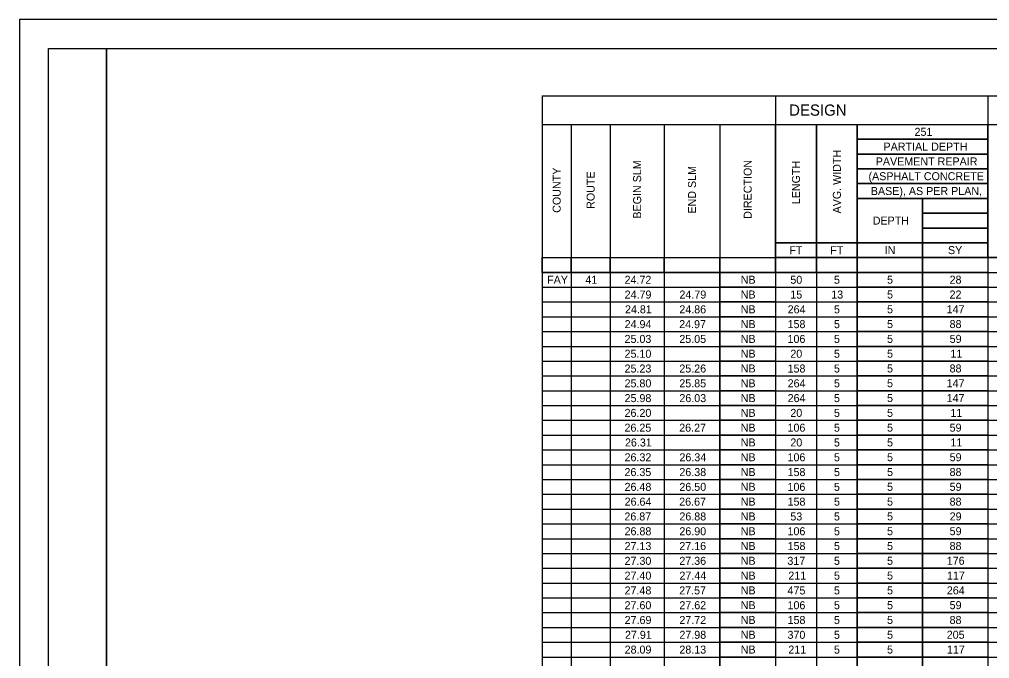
# Model space of a CAD drawing. Extents: x 0 to 34, y 0 to 22.
# Drawn here: x 0 to 16.72, y 10.98 to 22 of the extents above; entities that cross this region are included whole.
import ezdxf

# ---------------------------------------------------------------- set-up
doc = ezdxf.new("R2010")
doc.units = 0
for name, color, linetype in [('SH_Border', 7, 'Continuous'), ('SH_Cut_Line', 7, 'Continuous'), ('SH_Text', 7, 'Continuous')]:
    doc.layers.add(name, color=color, linetype=linetype)

msp = doc.modelspace()

# ---------------------------------------------------------------- linework, layer by layer
at = {"layer": 'SH_Border'}
for points in [[(0.5, 21.5), (1.5, 21.5), (1.5, 0.5), (0.5, 0.5)], [(1.5, 21.5), (33.5, 21.5), (33.5, 0.5), (1.5, 0.5)]]:
    msp.add_lwpolyline(points, close=True, dxfattribs=at)
at = {"layer": 'SH_Cut_Line'}
msp.add_lwpolyline([(0, 0), (34, 0), (34, 22), (0, 22)], close=True, dxfattribs=at)
at = {"layer": 'SH_Text'}
for p, q in [((9.014, 20.684), (23.069, 20.684)), ((9.014, 20.684), (9.014, 1.829)), ((13.034, 20.684), (13.034, 2.084)), ((16.694, 20.684), (16.694, 1.829)), ((9.014, 20.189), (23.069, 20.189)), ((9.509, 20.189), (9.509, 2.084)), ((10.184, 20.189), (10.184, 2.084)), ((11.114, 20.189), (11.114, 2.084)), ((12.074, 20.189), (12.074, 2.084)), ((13.739, 20.189), (13.739, 2.084)), ((14.444, 20.189), (14.444, 1.829)), ((14.444, 19.934), (16.694, 19.934)), ((14.444, 18.914), (15.569, 18.914)), ((15.569, 18.914), (15.569, 2.084)), ((13.034, 18.149), (16.694, 18.149)), ((9.014, 17.894), (23.069, 17.894)), ((9.014, 17.639), (23.069, 17.639)), ((9.014, 17.384), (23.069, 17.384)), ((9.014, 17.129), (23.069, 17.129)), ((9.014, 16.874), (23.069, 16.874)), ((9.014, 16.619), (23.069, 16.619)), ((9.014, 16.364), (23.069, 16.364)), ((9.014, 16.109), (23.069, 16.109)), ((9.014, 15.854), (23.069, 15.854)), ((9.014, 15.599), (23.069, 15.599)), ((9.014, 15.344), (23.069, 15.344)), ((9.014, 15.089), (23.069, 15.089)), ((9.014, 14.834), (23.069, 14.834)), ((9.014, 14.579), (23.069, 14.579)), ((9.014, 14.324), (23.069, 14.324)), ((9.014, 14.069), (23.069, 14.069)), ((9.014, 13.814), (23.069, 13.814)), ((9.014, 13.559), (23.069, 13.559)), ((9.014, 13.304), (23.069, 13.304)), ((9.014, 13.049), (23.069, 13.049)), ((9.014, 12.794), (23.069, 12.794)), ((9.014, 12.539), (23.069, 12.539)), ((9.014, 12.284), (23.069, 12.284)), ((9.014, 12.029), (23.069, 12.029)), ((9.014, 11.774), (23.069, 11.774)), ((9.014, 11.519), (23.069, 11.519)), ((9.014, 11.264), (23.069, 11.264)), ((9.014, 11.009), (23.069, 11.009))]:
    msp.add_line(p, q, dxfattribs=at)
for points in [[(13.034, 20.189), (13.739, 20.189), (13.739, 18.149), (13.034, 18.149)], [(13.739, 20.189), (14.444, 20.189), (14.444, 18.149), (13.739, 18.149)], [(14.444, 20.189), (16.694, 20.189), (16.694, 19.934), (14.444, 19.934)], [(16.694, 20.189), (23.069, 20.189), (23.069, 17.894), (16.694, 17.894)], [(14.444, 19.934), (16.694, 19.934), (16.694, 19.679), (14.444, 19.679)], [(14.444, 19.679), (16.694, 19.679), (16.694, 19.424), (14.444, 19.424)], [(14.444, 19.424), (16.694, 19.424), (16.694, 19.169), (14.444, 19.169)], [(14.444, 19.169), (16.694, 19.169), (16.694, 18.914), (14.444, 18.914)], [(14.444, 18.914), (15.569, 18.914), (15.569, 18.149), (14.444, 18.149)], [(15.569, 18.914), (16.694, 18.914), (16.694, 18.659), (15.569, 18.659)], [(15.569, 18.659), (16.694, 18.659), (16.694, 18.404), (15.569, 18.404)], [(15.569, 18.404), (16.694, 18.404), (16.694, 18.149), (15.569, 18.149)], [(13.034, 18.149), (13.739, 18.149), (13.739, 17.894), (13.034, 17.894)], [(13.739, 18.149), (14.444, 18.149), (14.444, 17.894), (13.739, 17.894)], [(14.444, 18.149), (15.569, 18.149), (15.569, 17.894), (14.444, 17.894)], [(15.569, 18.149), (16.694, 18.149), (16.694, 17.894), (15.569, 17.894)], [(9.014, 17.894), (9.509, 17.894), (9.509, 17.639), (9.014, 17.639)], [(9.509, 17.894), (10.184, 17.894), (10.184, 17.639), (9.509, 17.639)], [(10.184, 17.894), (11.114, 17.894), (11.114, 17.639), (10.184, 17.639)], [(11.114, 17.894), (12.074, 17.894), (12.074, 17.639), (11.114, 17.639)], [(12.074, 17.894), (13.034, 17.894), (13.034, 17.639), (12.074, 17.639)], [(13.034, 17.894), (13.739, 17.894), (13.739, 17.639), (13.034, 17.639)], [(13.739, 17.894), (14.444, 17.894), (14.444, 17.639), (13.739, 17.639)], [(14.444, 17.894), (15.569, 17.894), (15.569, 17.639), (14.444, 17.639)], [(15.569, 17.894), (16.694, 17.894), (16.694, 17.639), (15.569, 17.639)], [(12.074, 17.639), (13.034, 17.639), (13.034, 17.384), (12.074, 17.384)], [(14.444, 17.639), (15.569, 17.639), (15.569, 17.384), (14.444, 17.384)], [(15.569, 17.639), (16.694, 17.639), (16.694, 17.384), (15.569, 17.384)], [(12.074, 17.384), (13.034, 17.384), (13.034, 17.129), (12.074, 17.129)], [(14.444, 17.384), (15.569, 17.384), (15.569, 17.129), (14.444, 17.129)], [(15.569, 17.384), (16.694, 17.384), (16.694, 17.129), (15.569, 17.129)], [(12.074, 17.129), (13.034, 17.129), (13.034, 16.874), (12.074, 16.874)], [(14.444, 17.129), (15.569, 17.129), (15.569, 16.874), (14.444, 16.874)], [(15.569, 17.129), (16.694, 17.129), (16.694, 16.874), (15.569, 16.874)], [(12.074, 16.874), (13.034, 16.874), (13.034, 16.619), (12.074, 16.619)], [(14.444, 16.874), (15.569, 16.874), (15.569, 16.619), (14.444, 16.619)], [(15.569, 16.874), (16.694, 16.874), (16.694, 16.619), (15.569, 16.619)], [(12.074, 16.619), (13.034, 16.619), (13.034, 16.364), (12.074, 16.364)], [(14.444, 16.619), (15.569, 16.619), (15.569, 16.364), (14.444, 16.364)], [(15.569, 16.619), (16.694, 16.619), (16.694, 16.364), (15.569, 16.364)], [(12.074, 16.364), (13.034, 16.364), (13.034, 16.109), (12.074, 16.109)], [(14.444, 16.364), (15.569, 16.364), (15.569, 16.109), (14.444, 16.109)], [(15.569, 16.364), (16.694, 16.364), (16.694, 16.109), (15.569, 16.109)], [(12.074, 16.109), (13.034, 16.109), (13.034, 15.854), (12.074, 15.854)], [(14.444, 16.109), (15.569, 16.109), (15.569, 15.854), (14.444, 15.854)], [(15.569, 16.109), (16.694, 16.109), (16.694, 15.854), (15.569, 15.854)], [(12.074, 15.854), (13.034, 15.854), (13.034, 15.599), (12.074, 15.599)], [(14.444, 15.854), (15.569, 15.854), (15.569, 15.599), (14.444, 15.599)], [(15.569, 15.854), (16.694, 15.854), (16.694, 15.599), (15.569, 15.599)], [(12.074, 15.599), (13.034, 15.599), (13.034, 15.344), (12.074, 15.344)], [(14.444, 15.599), (15.569, 15.599), (15.569, 15.344), (14.444, 15.344)], [(15.569, 15.599), (16.694, 15.599), (16.694, 15.344), (15.569, 15.344)], [(12.074, 15.344), (13.034, 15.344), (13.034, 15.089), (12.074, 15.089)], [(14.444, 15.344), (15.569, 15.344), (15.569, 15.089), (14.444, 15.089)], [(15.569, 15.344), (16.694, 15.344), (16.694, 15.089), (15.569, 15.089)], [(12.074, 15.089), (13.034, 15.089), (13.034, 14.834), (12.074, 14.834)], [(14.444, 15.089), (15.569, 15.089), (15.569, 14.834), (14.444, 14.834)], [(15.569, 15.089), (16.694, 15.089), (16.694, 14.834), (15.569, 14.834)], [(12.074, 14.834), (13.034, 14.834), (13.034, 14.579), (12.074, 14.579)], [(14.444, 14.834), (15.569, 14.834), (15.569, 14.579), (14.444, 14.579)], [(15.569, 14.834), (16.694, 14.834), (16.694, 14.579), (15.569, 14.579)], [(12.074, 14.579), (13.034, 14.579), (13.034, 14.324), (12.074, 14.324)], [(14.444, 14.579), (15.569, 14.579), (15.569, 14.324), (14.444, 14.324)], [(15.569, 14.579), (16.694, 14.579), (16.694, 14.324), (15.569, 14.324)], [(12.074, 14.324), (13.034, 14.324), (13.034, 14.069), (12.074, 14.069)], [(14.444, 14.324), (15.569, 14.324), (15.569, 14.069), (14.444, 14.069)], [(15.569, 14.324), (16.694, 14.324), (16.694, 14.069), (15.569, 14.069)], [(12.074, 14.069), (13.034, 14.069), (13.034, 13.814), (12.074, 13.814)], [(14.444, 14.069), (15.569, 14.069), (15.569, 13.814), (14.444, 13.814)], [(15.569, 14.069), (16.694, 14.069), (16.694, 13.814), (15.569, 13.814)], [(12.074, 13.814), (13.034, 13.814), (13.034, 13.559), (12.074, 13.559)], [(14.444, 13.814), (15.569, 13.814), (15.569, 13.559), (14.444, 13.559)], [(15.569, 13.814), (16.694, 13.814), (16.694, 13.559), (15.569, 13.559)], [(12.074, 13.559), (13.034, 13.559), (13.034, 13.304), (12.074, 13.304)], [(14.444, 13.559), (15.569, 13.559), (15.569, 13.304), (14.444, 13.304)], [(15.569, 13.559), (16.694, 13.559), (16.694, 13.304), (15.569, 13.304)], [(12.074, 13.304), (13.034, 13.304), (13.034, 13.049), (12.074, 13.049)], [(14.444, 13.304), (15.569, 13.304), (15.569, 13.049), (14.444, 13.049)], [(15.569, 13.304), (16.694, 13.304), (16.694, 13.049), (15.569, 13.049)], [(12.074, 13.049), (13.034, 13.049), (13.034, 12.794), (12.074, 12.794)], [(14.444, 13.049), (15.569, 13.049), (15.569, 12.794), (14.444, 12.794)], [(15.569, 13.049), (16.694, 13.049), (16.694, 12.794), (15.569, 12.794)], [(12.074, 12.794), (13.034, 12.794), (13.034, 12.539), (12.074, 12.539)], [(14.444, 12.794), (15.569, 12.794), (15.569, 12.539), (14.444, 12.539)], [(15.569, 12.794), (16.694, 12.794), (16.694, 12.539), (15.569, 12.539)], [(12.074, 12.539), (13.034, 12.539), (13.034, 12.284), (12.074, 12.284)], [(14.444, 12.539), (15.569, 12.539), (15.569, 12.284), (14.444, 12.284)], [(15.569, 12.539), (16.694, 12.539), (16.694, 12.284), (15.569, 12.284)], [(12.074, 12.284), (13.034, 12.284), (13.034, 12.029), (12.074, 12.029)], [(14.444, 12.284), (15.569, 12.284), (15.569, 12.029), (14.444, 12.029)], [(15.569, 12.284), (16.694, 12.284), (16.694, 12.029), (15.569, 12.029)], [(12.074, 12.029), (13.034, 12.029), (13.034, 11.774), (12.074, 11.774)], [(14.444, 12.029), (15.569, 12.029), (15.569, 11.774), (14.444, 11.774)], [(15.569, 12.029), (16.694, 12.029), (16.694, 11.774), (15.569, 11.774)], [(12.074, 11.774), (13.034, 11.774), (13.034, 11.519), (12.074, 11.519)], [(14.444, 11.774), (15.569, 11.774), (15.569, 11.519), (14.444, 11.519)], [(15.569, 11.774), (16.694, 11.774), (16.694, 11.519), (15.569, 11.519)], [(12.074, 11.519), (13.034, 11.519), (13.034, 11.264), (12.074, 11.264)], [(14.444, 11.519), (15.569, 11.519), (15.569, 11.264), (14.444, 11.264)], [(15.569, 11.519), (16.694, 11.519), (16.694, 11.264), (15.569, 11.264)], [(12.074, 11.264), (13.034, 11.264), (13.034, 11.009), (12.074, 11.009)], [(14.444, 11.264), (15.569, 11.264), (15.569, 11.009), (14.444, 11.009)], [(15.569, 11.264), (16.694, 11.264), (16.694, 11.009), (15.569, 11.009)], [(12.074, 11.009), (13.034, 11.009), (13.034, 10.754), (12.074, 10.754)], [(14.444, 11.009), (15.569, 11.009), (15.569, 10.754), (14.444, 10.754)], [(15.569, 11.009), (16.694, 11.009), (16.694, 10.754), (15.569, 10.754)]]:
    msp.add_lwpolyline(points, close=True, dxfattribs=at)

# ---------------------------------------------------------------- texts
for s, height, p in [('DESIGN', 0.1932, (13.269, 20.34)), ('251', 0.138, (15.431, 19.993)), ('PARTIAL DEPTH', 0.138, (14.896, 19.738)), ('PAVEMENT REPAIR', 0.138, (14.762, 19.483)), ('(ASPHALT CONCRETE', 0.138, (14.637, 19.228)), ('BASE), AS PER PLAN,', 0.138, (14.677, 18.973)), ('DEPTH', 0.138, (14.71, 18.463)), ('FT', 0.138, (13.272, 17.953)), ('FT', 0.138, (13.977, 17.953)), ('IN', 0.138, (14.917, 17.954)), ('SY', 0.138, (16.007, 17.954)), ('FAY', 0.138, (9.097, 17.443)), ('41', 0.138, (9.757, 17.443)), ('24.72', 0.138, (10.432, 17.443)), ('NB', 0.138, (12.434, 17.444)), ('50', 0.138, (13.29, 17.443)), ('5', 0.138, (14.042, 17.443)), ('5', 0.138, (14.957, 17.444)), ('28', 0.138, (16.035, 17.444)), ('24.79', 0.138, (10.433, 17.188)), ('24.79', 0.138, (11.378, 17.188)), ('NB', 0.138, (12.434, 17.189)), ('15', 0.138, (13.289, 17.188)), ('13', 0.138, (13.995, 17.188)), ('5', 0.138, (14.957, 17.189)), ('22', 0.138, (16.035, 17.189)), ('24.81', 0.138, (10.439, 16.933)), ('24.86', 0.138, (11.376, 16.933)), ('NB', 0.138, (12.434, 16.934)), ('264', 0.138, (13.243, 16.933)), ('5', 0.138, (14.042, 16.933)), ('5', 0.138, (14.957, 16.934)), ('147', 0.138, (15.984, 16.934)), ('24.94', 0.138, (10.433, 16.678)), ('24.97', 0.138, (11.374, 16.678)), ('NB', 0.138, (12.434, 16.679)), ('158', 0.138, (13.242, 16.678)), ('5', 0.138, (14.042, 16.678)), ('5', 0.138, (14.957, 16.679)), ('88', 0.138, (16.035, 16.679)), ('25.03', 0.138, (10.432, 16.423)), ('25.05', 0.138, (11.376, 16.423)), ('NB', 0.138, (12.434, 16.424)), ('106', 0.138, (13.241, 16.423)), ('5', 0.138, (14.042, 16.423)), ('5', 0.138, (14.957, 16.424)), ('59', 0.138, (16.036, 16.424)), ('25.10', 0.138, (10.432, 16.168)), ('NB', 0.138, (12.434, 16.169)), ('20', 0.138, (13.29, 16.168)), ('5', 0.138, (14.042, 16.168)), ('5', 0.138, (14.957, 16.169)), ('11', 0.138, (16.049, 16.169)), ('25.23', 0.138, (10.432, 15.913)), ('25.26', 0.138, (11.376, 15.913)), ('NB', 0.138, (12.434, 15.914)), ('158', 0.138, (13.242, 15.913)), ('5', 0.138, (14.042, 15.913)), ('5', 0.138, (14.957, 15.914)), ('88', 0.138, (16.035, 15.914)), ('25.80', 0.138, (10.432, 15.658)), ('25.85', 0.138, (11.376, 15.658)), ('NB', 0.138, (12.434, 15.659)), ('264', 0.138, (13.243, 15.658)), ('5', 0.138, (14.042, 15.658)), ('5', 0.138, (14.957, 15.659)), ('147', 0.138, (15.984, 15.659)), ('25.98', 0.138, (10.432, 15.403)), ('26.03', 0.138, (11.377, 15.403)), ('NB', 0.138, (12.434, 15.404)), ('264', 0.138, (13.243, 15.403)), ('5', 0.138, (14.042, 15.403)), ('5', 0.138, (14.957, 15.404)), ('147', 0.138, (15.984, 15.404)), ('26.20', 0.138, (10.432, 15.148)), ('NB', 0.138, (12.434, 15.149)), ('20', 0.138, (13.29, 15.148)), ('5', 0.138, (14.042, 15.148)), ('5', 0.138, (14.957, 15.149)), ('11', 0.138, (16.049, 15.149)), ('26.25', 0.138, (10.431, 14.893)), ('26.27', 0.138, (11.374, 14.893)), ('NB', 0.138, (12.434, 14.894)), ('106', 0.138, (13.241, 14.893)), ('5', 0.138, (14.042, 14.893)), ('5', 0.138, (14.957, 14.894)), ('59', 0.138, (16.036, 14.894)), ('26.31', 0.138, (10.439, 14.638)), ('NB', 0.138, (12.434, 14.639)), ('20', 0.138, (13.29, 14.638)), ('5', 0.138, (14.042, 14.638)), ('5', 0.138, (14.957, 14.639)), ('11', 0.138, (16.049, 14.639)), ('26.32', 0.138, (10.432, 14.383)), ('26.34', 0.138, (11.378, 14.383)), ('NB', 0.138, (12.434, 14.384)), ('106', 0.138, (13.241, 14.383)), ('5', 0.138, (14.042, 14.383)), ('5', 0.138, (14.957, 14.384)), ('59', 0.138, (16.036, 14.384)), ('26.35', 0.138, (10.431, 14.128)), ('26.38', 0.138, (11.377, 14.128)), ('NB', 0.138, (12.434, 14.129)), ('158', 0.138, (13.242, 14.128)), ('5', 0.138, (14.042, 14.128)), ('5', 0.138, (14.957, 14.129)), ('88', 0.138, (16.035, 14.129)), ('26.48', 0.138, (10.432, 13.873)), ('26.50', 0.138, (11.377, 13.873)), ('NB', 0.138, (12.434, 13.874)), ('106', 0.138, (13.241, 13.873)), ('5', 0.138, (14.042, 13.873)), ('5', 0.138, (14.957, 13.874)), ('59', 0.138, (16.036, 13.874)), ('26.64', 0.138, (10.433, 13.618)), ('26.67', 0.138, (11.374, 13.618)), ('NB', 0.138, (12.434, 13.619)), ('158', 0.138, (13.242, 13.618)), ('5', 0.138, (14.042, 13.618)), ('5', 0.138, (14.957, 13.619)), ('88', 0.138, (16.035, 13.619)), ('26.87', 0.138, (10.429, 13.363)), ('26.88', 0.138, (11.377, 13.363)), ('NB', 0.138, (12.434, 13.364)), ('53', 0.138, (13.29, 13.363)), ('5', 0.138, (14.042, 13.363)), ('5', 0.138, (14.957, 13.364)), ('29', 0.138, (16.036, 13.364)), ('26.88', 0.138, (10.432, 13.108)), ('26.90', 0.138, (11.377, 13.108)), ('NB', 0.138, (12.434, 13.109)), ('106', 0.138, (13.241, 13.108)), ('5', 0.138, (14.042, 13.108)), ('5', 0.138, (14.957, 13.109)), ('59', 0.138, (16.036, 13.109)), ('27.13', 0.138, (10.432, 12.853)), ('27.16', 0.138, (11.376, 12.853)), ('NB', 0.138, (12.434, 12.854)), ('158', 0.138, (13.242, 12.853)), ('5', 0.138, (14.042, 12.853)), ('5', 0.138, (14.957, 12.854)), ('88', 0.138, (16.035, 12.854)), ('27.30', 0.138, (10.432, 12.598)), ('27.36', 0.138, (11.376, 12.598)), ('NB', 0.138, (12.434, 12.599)), ('317', 0.138, (13.239, 12.598)), ('5', 0.138, (14.042, 12.598)), ('5', 0.138, (14.957, 12.599)), ('176', 0.138, (15.986, 12.599)), ('27.40', 0.138, (10.432, 12.343)), ('27.44', 0.138, (11.378, 12.343)), ('NB', 0.138, (12.434, 12.344)), ('211', 0.138, (13.255, 12.343)), ('5', 0.138, (14.042, 12.343)), ('5', 0.138, (14.957, 12.344)), ('117', 0.138, (15.99, 12.344)), ('27.48', 0.138, (10.432, 12.088)), ('27.57', 0.138, (11.374, 12.088)), ('NB', 0.138, (12.434, 12.089)), ('475', 0.138, (13.241, 12.088)), ('5', 0.138, (14.042, 12.088)), ('5', 0.138, (14.957, 12.089)), ('264', 0.138, (15.988, 12.089)), ('27.60', 0.138, (10.432, 11.833)), ('27.62', 0.138, (11.377, 11.833)), ('NB', 0.138, (12.434, 11.834)), ('106', 0.138, (13.241, 11.833)), ('5', 0.138, (14.042, 11.833)), ('5', 0.138, (14.957, 11.834)), ('59', 0.138, (16.036, 11.834)), ('27.69', 0.138, (10.433, 11.578)), ('27.72', 0.138, (11.377, 11.578)), ('NB', 0.138, (12.434, 11.579)), ('158', 0.138, (13.242, 11.578)), ('5', 0.138, (14.042, 11.578)), ('5', 0.138, (14.957, 11.579)), ('88', 0.138, (16.035, 11.579)), ('27.91', 0.138, (10.439, 11.323)), ('27.98', 0.138, (11.377, 11.323)), ('NB', 0.138, (12.434, 11.324)), ('370', 0.138, (13.241, 11.323)), ('5', 0.138, (14.042, 11.323)), ('5', 0.138, (14.957, 11.324)), ('205', 0.138, (15.986, 11.324)), ('28.09', 0.138, (10.433, 11.068)), ('28.13', 0.138, (11.377, 11.068)), ('NB', 0.138, (12.434, 11.069)), ('211', 0.138, (13.255, 11.068)), ('5', 0.138, (14.042, 11.068)), ('5', 0.138, (14.957, 11.069)), ('117', 0.138, (15.99, 11.069))]:
    msp.add_text(s, height=height, dxfattribs=at).set_placement(p)
for s, p in [('AVG. WIDTH', (14.161, 18.655)), ('COUNTY', (9.331, 18.666)), ('BEGIN SLM', (10.718, 18.566)), ('END SLM', (11.663, 18.653)), ('DIRECTION', (12.623, 18.562)), ('LENGTH', (13.456, 18.814)), ('ROUTE', (9.916, 18.734))]:
    msp.add_text(s, height=0.138, rotation=90, dxfattribs=at).set_placement(p)

doc.saveas('drawing.dxf')
